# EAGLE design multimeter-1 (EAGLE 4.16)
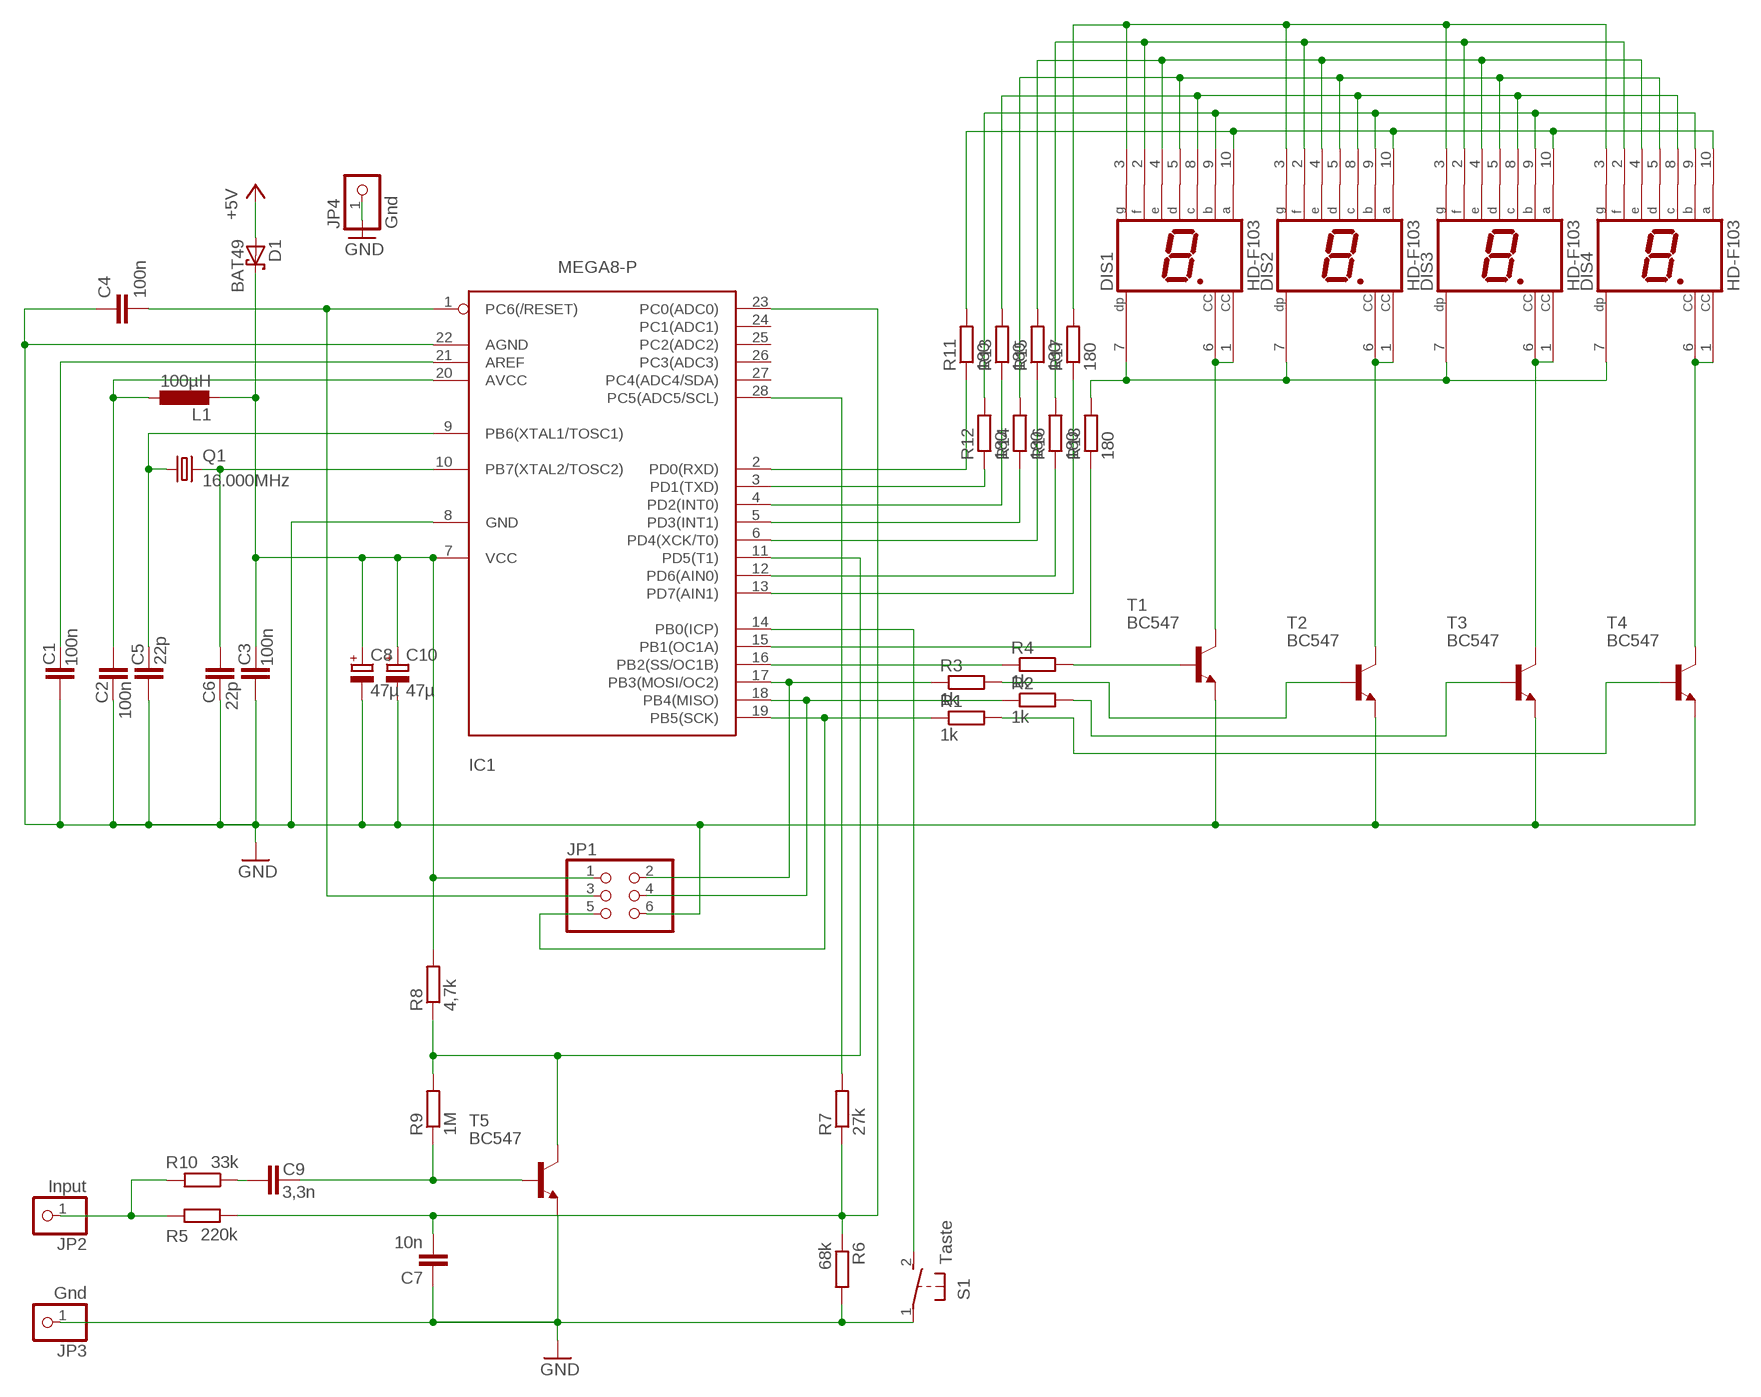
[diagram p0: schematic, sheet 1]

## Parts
C1  100n  C-EU025-030X050  [C025-030X050]
C2  100n  C-EU025-030X050  [C025-030X050]
C3  100n  C-EU025-030X050  [C025-030X050]
C4  100n  C-EU025-030X050  [C025-030X050]
C5  22p  C-EU025-030X050  [C025-030X050]
C6  22p  C-EU025-030X050  [C025-030X050]
C7  10n  C-EU025-030X050  [C025-030X050]
C8  47µ  CPOL-EUE2.5-5  [E2,5-5]
C9  3,3n  C-EU025-030X050  [C025-030X050]
C10  47µ  CPOL-EUE2.5-5  [E2,5-5]
D1  BAT49  [DO41-10]
DIS1  HD-F103  [HDSP-E]
DIS2  HD-F103  [HDSP-E]
DIS3  HD-F103  [HDSP-E]
DIS4  HD-F103  [HDSP-E]
IC1  MEGA8-P  [DIL28-3]
JP1  PINHD-2X3  [2X03]
JP2  Input  PINHD-1X1  [1X01]
JP3  Gnd  PINHD-1X1  [1X01]
JP4  Gnd  PINHD-1X1  [1X01]
L1  100µH  L-EU0207/2V  [0207/2V]
Q1  16.000MHz  CRYSTALHC49S  [HC49/S]
R1  1k  R-EU_0204/7  [0204/7]
R2  1k  R-EU_0204/7  [0204/7]
R3  1k  R-EU_0204/7  [0204/7]
R4  1k  R-EU_0204/7  [0204/7]
R5  220k  R-EU_0204/7  [0204/7]
R6  68k  R-EU_0204/7  [0204/7]
R7  27k  R-EU_0204/7  [0204/7]
R8  4,7k  R-EU_0204/7  [0204/7]
R9  1M  R-EU_0204/7  [0204/7]
R10  33k  R-EU_0204/7  [0204/7]
R11  180  R-EU_0204/7  [0204/7]
R12  180  R-EU_0204/7  [0204/7]
R13  180  R-EU_0204/7  [0204/7]
R14  180  R-EU_0204/7  [0204/7]
R15  180  R-EU_0204/7  [0204/7]
R16  180  R-EU_0204/7  [0204/7]
R17  180  R-EU_0204/7  [0204/7]
R18  180  R-EU_0204/7  [0204/7]
S1  Taste  31-XX  [B3F-31XX]
T1  BC547  [TO92]
T2  BC547  [TO92]
T3  BC547  [TO92]
T4  BC547  [TO92]
T5  BC547  [TO92]

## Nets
+5V: D1.A
GND: C1.1 C2.1 C3.1 C4.1 C5.1 C6.1 C7.1 C8.- C10.- IC1.8(GND) IC1.22(AGND) JP1.6 JP3.1 JP4.1 R6.2 S1.1(P) T1.1(E) T2.1(E) T3.1(E) T4.1(E) T5.1(E)
N$1: C4.2 IC1.1(PC6(/RESET)) JP1.3
N$2: C1.2 IC1.21(AREF)
N$3: C2.2 IC1.20(AVCC) L1.1
N$4: IC1.3(PD1(TXD)) R12.1
N$5: C5.2 IC1.9(PB6(XTAL1/TOSC1)) Q1.1
N$6: C6.2 IC1.10(PB7(XTAL2/TOSC2)) Q1.2
N$7: IC1.4(PD2(INT0)) R13.1
N$8: DIS1.10(A) DIS2.10(A) DIS3.10(A) DIS4.10(A) R11.2
N$9: DIS1.9(B) DIS2.9(B) DIS3.9(B) DIS4.9(B) R12.2
N$10: DIS1.8(C) DIS2.8(C) DIS3.8(C) DIS4.8(C) R13.2
N$11: DIS1.5(D) DIS2.5(D) DIS3.5(D) DIS4.5(D) R14.2
N$12: DIS1.4(E) DIS2.4(E) DIS3.4(E) DIS4.4(E) R15.2
N$13: DIS1.3(G) DIS2.3(G) DIS3.3(G) DIS4.3(G) R17.2
N$14: DIS1.2(F) DIS2.2(F) DIS3.2(F) DIS4.2(F) R16.2
N$15: DIS1.7(DP) DIS2.7(DP) DIS3.7(DP) DIS4.7(DP) R18.2
N$16: DIS1.1(CC) DIS1.6(CC) T1.3(C)
N$17: DIS2.1(CC) DIS2.6(CC) T2.3(C)
N$18: DIS3.1(CC) DIS3.6(CC) T3.3(C)
N$19: DIS4.1(CC) DIS4.6(CC) T4.3(C)
N$20: IC1.19(PB5(SCK)) JP1.5 R1.1
N$21: IC1.5(PD3(INT1)) R14.1
N$22: IC1.2(PD0(RXD)) R11.1
N$23: IC1.6(PD4(XCK/T0)) R15.1
N$24: IC1.12(PD6(AIN0)) R16.1
N$25: IC1.13(PD7(AIN1)) R17.1
N$26: IC1.15(PB1(OC1A)) R18.1
N$27: IC1.18(PB4(MISO)) JP1.4 R2.1
N$28: IC1.17(PB3(MOSI/OC2)) JP1.2 R3.1
N$29: IC1.16(PB2(SS/OC1B)) R4.1
N$30: R4.2 T1.2(B)
N$31: R3.2 T2.2(B)
N$32: R2.2 T3.2(B)
N$33: R1.2 T4.2(B)
N$34: C7.2 IC1.23(PC0(ADC0)) R5.2 R6.1 R7.1
N$35: C9.2 R10.1
N$36: JP2.1 R5.1 R10.2
N$37: IC1.14(PB0(ICP)) S1.2(S)
N$38: IC1.28(PC5(ADC5/SCL)) R7.2
N$40: IC1.11(PD5(T1)) R8.1 R9.2 T5.3(C)
N$42: C9.1 R9.1 T5.2(B)
VCC: C3.2 C8.+ C10.+ D1.C IC1.7(VCC) JP1.1 L1.2 R8.2
Unconnected: IC1.24(PC1(ADC1)) IC1.25(PC2(ADC2)) IC1.26(PC3(ADC3)) IC1.27(PC4(ADC4/SDA))

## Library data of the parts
C1-C7 C9 = rcl:C-EU: CAPACITOR, European symbol
C8 C10 = rcl:CPOL-EU: POLARIZED CAPACITOR, European symbol
D1 = diode:BAT49: DIODE
DIS1-DIS4 = display-hp:HD-F103: LED DISPLAY 1-character 7 segment, decimal point right
IC1 = atmel:MEGA8-P: MICROCONTROLLER 8 Kbytes FLASH 1 kbytes SRAM 512 bytes EEPROM USART 4-channel 10 bit ADC 2-channel 8 bit ADC Source: avr.lbr
JP1 = pinhead:PINHD-2X3: PIN HEADER
JP2-JP4 = pinhead:PINHD-1X1: PIN HEADER
L1 = rcl:L-EU: INDUCTOR, European symbol
Q1 = crystal:CRYSTAL: CRYSTAL
R1-R18 = rcl:R-EU_: RESISTOR, European symbol
S1 = switch-omron:31-XX: OMRON SWITCH
T1-T5 = transistor:BC547: NPN TRANSISTOR

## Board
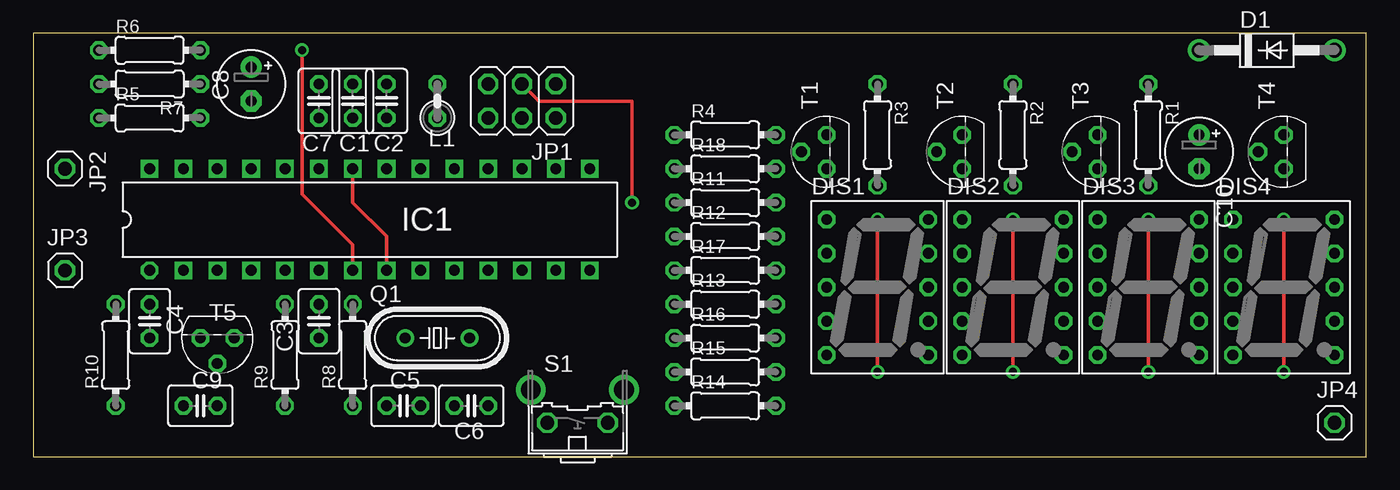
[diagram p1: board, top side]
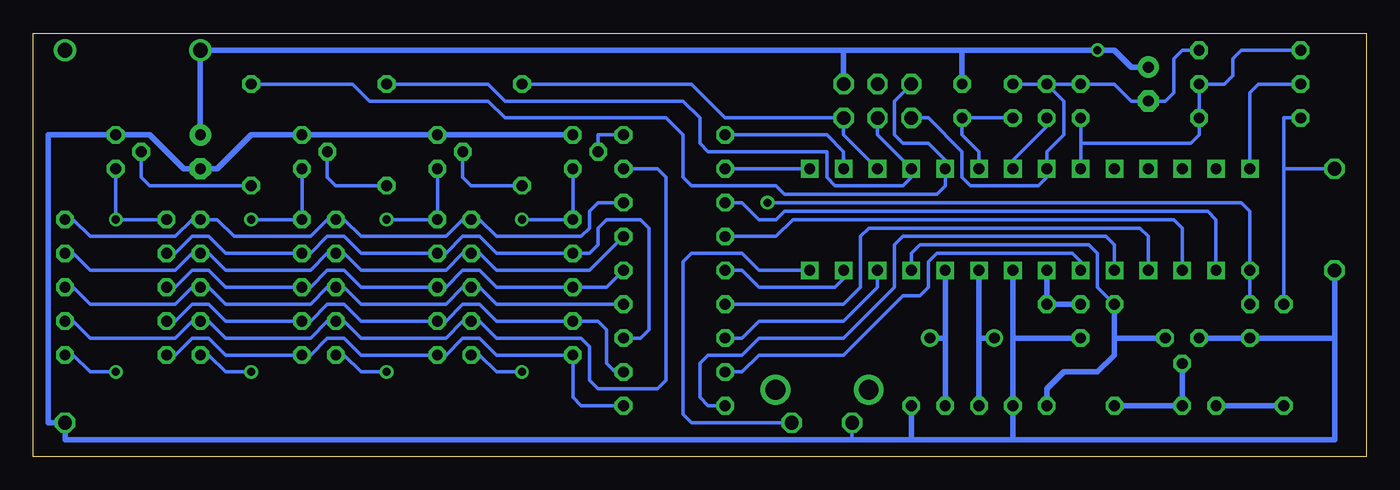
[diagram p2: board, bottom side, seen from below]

Size 100 x 31.74 mm. Coordinates in mm from the lower left corner, seen from the top.
Outline: 0,0 100,0 100,31.74 0,31.74 0,0
Copper layers (1*16): Top 0.035mm / dielectric 1.5mm / Bottom 0.035mm
Design rules "default": minimum track width 10mil, minimum drill 24mil, track to track 8mil, track to pad 8mil, pad to pad 8mil, via to via 8mil, smd to smd 8mil, copper to edge 40mil, drill to drill 8mil, minimum pad ring 10mil, minimum via ring 8mil, stop-mask expansion 4mil, vias tented up to drill 0mil, thermal gap 10mil

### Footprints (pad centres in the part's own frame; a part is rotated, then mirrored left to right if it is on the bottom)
C025-030X050 = drill 0.813 octagon: 1 -1.27,0; 2 1.27,0
E2,5-5 = drill 0.813 pad 1.6 round: + -1.27,0 | drill 0.813 pad 1.6 octagon: - 1.27,0
DO41-10 = drill 1.118 round: A 5.08,0; C -5.08,0
HDSP-E = drill 0.813 octagon: 1 -3.81,5.08; 2 -3.81,2.54; 3 -3.81,0; 4 -3.81,-2.54; 5 -3.81,-5.08; 6 3.81,-5.08; 7 3.81,-2.54; 8 3.81,0; 9 3.81,2.54; 10 3.81,5.08
DIL28-3 = drill 0.813 octagon: 1 -16.51,-3.81 | drill 0.813 square: 2 -13.97,-3.81; 3 -11.43,-3.81; 4 -8.89,-3.81; 5 -6.35,-3.81; 6 -3.81,-3.81; 7 -1.27,-3.81; 8 1.27,-3.81; 9 3.81,-3.81; 10 6.35,-3.81; 11 8.89,-3.81; 12 11.43,-3.81; 13 13.97,-3.81; 14 16.51,-3.81; 15 16.51,3.81; 16 13.97,3.81; 17 11.43,3.81; 18 8.89,3.81; 19 6.35,3.81; 20 3.81,3.81; 21 1.27,3.81; 22 -1.27,3.81; 23 -3.81,3.81; 24 -6.35,3.81; 25 -8.89,3.81; 26 -11.43,3.81; 27 -13.97,3.81; 28 -16.51,3.81
2X03 = drill 1.016 octagon: 1 -2.54,-1.27; 2 -2.54,1.27; 3 0,-1.27; 4 0,1.27; 5 2.54,-1.27; 6 2.54,1.27
1X01 = drill 1.016 octagon: 1 0,0
0207/2V = drill 0.813 octagon: 1 -1.27,0; 2 1.27,0
HC49/S = drill 0.813 round: 1 -2.413,0; 2 2.413,0
0204/7 = drill 0.813 octagon: 1 -3.81,0; 2 3.81,0
B3F-31XX = drill 1.016 octagon: 1 -2.261,-1.245; 2 2.261,-1.245 | drill 1.499 pad 2.159 round: 3 -3.505,1.245; 4 3.505,1.245
TO92 = drill 0.813 octagon: 1 1.27,0; 2 0,1.905; 3 -1.27,0

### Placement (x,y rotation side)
C1  23.96,26.67 270 top
C2  26.51,26.67 270 top
C3  21.43,10.15 90 top
C4  8.73,10.15 90 top
C5  27.78,3.81 0 top
C6  32.86,3.81 180 top
C7  21.43,26.67 270 top
C8  16.35,27.94 270 top
C9  12.54,3.81 180 top
C10  87.46,22.86 270 top
D1  92.54,30.48 0 top
DIS1  63.34,12.69 0 top
DIS2  73.49,12.69 0 top
DIS3  83.65,12.69 0 top
DIS4  93.81,12.69 0 top
IC1  25.23,17.78 0 top
JP1  36.66,26.67 180 top
JP2  2.38,21.59 270 top
JP3  2.38,13.96 0 top
JP4  97.62,2.54 0 top
L1  30.32,26.67 90 top
Q1  30.32,8.88 0 top
R1  83.65,24.12 270 top
R2  73.49,24.12 270 top
R3  63.34,24.12 270 top
R4  51.91,24.12 0 top
R5  8.73,25.39 0 top
R6  8.73,30.48 0 top
R7  8.73,27.94 180 top
R8  23.96,7.62 90 top
R9  18.89,7.62 90 top
R10  6.18,7.62 90 top
R11  51.91,19.05 0 top
R12  51.91,16.51 0 top
R13  51.91,11.42 0 top
R14  51.91,3.81 0 top
R15  51.91,6.34 0 top
R16  51.91,8.88 0 top
R17  51.91,13.96 0 top
R18  51.91,21.59 0 top
S1  40.83,3.78 0 top
T1  59.52,22.86 90 top
T2  69.68,22.86 90 top
T3  79.84,22.86 90 top
T4  93.81,22.86 90 top
T5  13.81,8.88 180 top

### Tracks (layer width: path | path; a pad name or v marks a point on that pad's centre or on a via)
GND
  Top 0.254: IC1.8 26.51,16.51 23.96,19.05 IC1.22
  Bottom 0.254: C1.1 C7.1 18.89,27.94 17.62,26.67 C8.- 15.08,26.67 14.44,27.3 14.44,29.84 13.81,30.48 R6.2 | C1.1 22.7,26.67 22.7,24.12 23.96,22.86 IC1.22 23.96,20.95 24.6,20.32 29.68,20.32 30.32,20.95 30.32,22.86 32.86,25.39 JP1.6 | C1.1 C2.1 | 38.57,1.27 S1.1
  Bottom 0.406: 2.38,8.88 2.38,1.27 26.51,1.27 | 2.38,8.88 JP3.1 | 26.51,1.27 34.12,1.27 | 34.12,1.27 38.57,1.27 97.62,1.27 JP4.1 98.89,2.54 98.89,24.12 T4.1 91.27,24.12 88.73,21.59 C10.- 86.19,21.59 83.65,24.12 T3.1 T2.1 T1.1 | 26.51,8.88 C5.1 26.51,1.27 | 26.51,8.88 IC1.8 | 34.12,1.27 C6.1 | 26.51,8.88 C3.1 | T5.1 C4.1 2.38,8.88
N$1  (via drill 0.61)
  Top 0.254: v44.92,19.05 44.92,26.67 37.94,26.67 JP1.3
  Bottom 0.254: v44.92,19.05 9.36,19.05 8.73,18.41 IC1.1 C4.2
N$2
  Bottom 0.254: C1.2 23.96,24.76 26.51,22.22 IC1.21
N$3
  Bottom 0.254: C2.2 L1.1 30.32,24.12 29.05,22.86 IC1.20
N$4
  Bottom 0.254: IC1.3 13.81,17.14 14.44,17.78 43.02,17.78 44.29,16.51 R12.1
N$5
  Bottom 0.406: C5.2 29.05,8.88 | 29.05,8.88 IC1.9 | 29.05,8.88 Q1.1
N$6
  Bottom 0.406: C6.2 31.59,8.88 | 31.59,8.88 IC1.10 | 31.59,8.88 Q1.2
N$7
  Bottom 0.254: IC1.4 16.35,16.51 16.98,17.14 37.3,17.14 37.94,16.51 37.94,12.69 39.2,11.42 R13.1
N$8
  Bottom 0.254: DIS4.10 96.99,17.78 95.72,16.51 89.37,16.51 88.1,17.78 DIS3.10 86.19,17.78 84.92,16.51 79.21,16.51 77.94,17.78 DIS2.10 76.67,17.78 75.4,16.51 69.05,16.51 67.78,17.78 DIS1.10 66.51,17.78 65.24,16.51 58.89,16.51 58.26,17.14 58.26,18.41 57.62,19.05 R11.2
N$9
  Bottom 0.254: DIS4.9 96.99,15.23 95.72,13.96 89.37,13.96 88.1,15.23 DIS3.9 86.83,15.23 85.56,13.96 79.21,13.96 77.94,15.23 DIS2.9 76.67,15.23 75.4,13.96 69.05,13.96 67.78,15.23 DIS1.9 66.51,15.23 65.24,13.96 58.26,13.96 R12.2
N$10
  Bottom 0.254: DIS4.8 96.99,12.69 95.72,11.42 89.37,11.42 88.1,12.69 DIS3.8 86.83,12.69 85.56,11.42 79.21,11.42 77.94,12.69 DIS2.8 76.67,12.69 75.4,11.42 69.05,11.42 67.78,12.69 DIS1.8 66.51,12.69 65.24,11.42 R13.2
N$11
  Bottom 0.254: DIS4.5 89.37,7.62 88.1,8.88 86.83,8.88 85.56,7.62 DIS3.5 79.21,7.62 77.94,8.88 76.67,8.88 75.4,7.62 DIS2.5 69.05,7.62 67.78,8.88 66.51,8.88 65.24,7.62 DIS1.5 59.52,4.44 58.89,3.81 R14.2
N$12
  Bottom 0.254: DIS4.4 89.37,10.15 88.1,11.42 86.83,11.42 85.56,10.15 DIS3.4 79.21,10.15 77.94,11.42 76.67,11.42 75.4,10.15 DIS2.4 69.05,10.15 67.78,11.42 66.51,11.42 65.24,10.15 DIS1.4 57.62,10.15 56.98,9.52 56.98,6.98 56.35,6.34 R15.2
N$13
  Bottom 0.254: DIS4.3 89.37,12.69 88.1,13.96 86.83,13.96 85.56,12.69 DIS3.3 79.21,12.69 77.94,13.96 76.67,13.96 75.4,12.69 DIS2.3 69.05,12.69 67.78,13.96 66.51,13.96 65.24,12.69 DIS1.3 56.98,12.69 R17.2
N$14
  Bottom 0.254: DIS4.2 89.37,15.23 88.1,16.51 86.83,16.51 85.56,15.23 DIS3.2 79.21,15.23 77.94,16.51 76.67,16.51 75.4,15.23 DIS2.2 69.05,15.23 67.78,16.51 66.51,16.51 65.24,15.23 DIS1.2 58.26,15.23 57.62,15.87 57.62,17.14 56.98,17.78 54.45,17.78 53.81,17.14 53.81,9.52 54.45,8.88 R16.2
N$15
  Bottom 0.254: DIS4.7 96.99,10.15 95.72,8.88 89.37,8.88 88.1,10.15 DIS3.7 86.83,10.15 85.56,8.88 79.21,8.88 77.94,10.15 DIS2.7 76.67,10.15 75.4,8.88 69.05,8.88 67.78,10.15 DIS1.7 66.51,10.15 65.24,8.88 58.89,8.88 58.26,8.25 58.26,5.71 57.62,5.08 53.18,5.08 52.54,5.71 52.54,20.95 53.18,21.59 R18.2
N$16  (via drill 0.61 pad 1.02)
  Top 0.254: v63.34,6.34 v63.34,17.78
  Bottom 0.254: v63.34,6.34 65.24,6.34 66.51,7.62 DIS1.6 | v63.34,17.78 DIS1.1 T1.3
N$17  (via drill 0.61 pad 1.02)
  Top 0.254: v73.49,6.34 v73.49,17.78
  Bottom 0.254: v73.49,6.34 75.4,6.34 76.67,7.62 DIS2.6 | v73.49,17.78 DIS2.1 T2.3
N$18  (via drill 0.61 pad 1.02)
  Top 0.254: v83.65,6.34 v83.65,17.78
  Bottom 0.254: v83.65,6.34 85.56,6.34 86.83,7.62 DIS3.6 | v83.65,17.78 DIS3.1 T3.3
N$19  (via drill 0.61 pad 1.02)
  Top 0.254: v93.81,6.34 v93.81,17.78
  Bottom 0.254: v93.81,6.34 95.72,6.34 96.99,7.62 DIS4.6 | DIS4.1 v93.81,17.78 T4.3
N$20
  Bottom 0.254: JP1.5 35.4,26.67 35.4,24.12 34.76,23.49 32.86,23.49 31.59,22.22 IC1.19 31.59,20.32 32.22,19.68 43.65,19.68 44.29,20.32 50.63,20.32 51.27,20.95 51.27,24.12 52.54,25.39 64.6,25.39 65.88,26.67 74.77,26.67 76.03,27.94 R1.1
N$21
  Bottom 0.254: IC1.5 18.89,15.87 19.52,16.51 34.76,16.51 35.4,15.87 35.4,12.69 39.2,8.88 45.55,8.88 46.83,7.62 49.37,7.62 50,6.98 50,4.44 49.37,3.81 R14.1
N$22
  Bottom 0.254: IC1.2 11.27,17.78 11.9,18.41 43.65,18.41 44.29,17.78 45.55,17.78 46.83,19.05 R11.1
N$23
  Bottom 0.254: IC1.6 21.43,14.6 22.06,15.23 32.22,15.23 32.86,14.6 32.86,12.69 33.49,12.06 34.76,12.06 39.2,7.62 45.55,7.62 46.83,6.34 R15.1
N$24
  Bottom 0.254: IC1.12 36.66,12.69 39.2,10.15 45.55,10.15 46.83,8.88 R16.1
N$25
  Bottom 0.254: IC1.13 39.2,13.33 39.84,12.69 45.55,12.69 46.83,13.96 R17.1
N$26
  Bottom 0.254: IC1.15 R18.1
N$27
  Bottom 0.254: R2.1 65.88,27.94 64.6,26.67 51.27,26.67 50,25.39 50,23.49 49.37,22.86 40.48,22.86 40.48,20.95 39.84,20.32 34.76,20.32 34.12,20.95 IC1.18 36.66,24.12 JP1.4
N$28
  Bottom 0.254: R3.1 50.63,27.94 48.09,25.39 JP1.2 39.2,24.12 IC1.17
N$29
  Bottom 0.254: IC1.16 39.2,22.86 40.48,24.12 R4.1
N$30
  Bottom 0.254: T1.2 57.62,24.12 R4.2
N$31
  Bottom 0.254: T2.2 67.78,20.95 67.14,20.32 R3.2
N$32
  Bottom 0.254: T3.2 77.94,20.95 77.3,20.32 R2.2
N$33
  Bottom 0.254: T4.2 91.91,20.95 91.27,20.32 R1.2
N$34
  Bottom 0.254: 21.43,23.49 C7.2 | 21.43,23.49 IC1.23 | 21.43,23.49 13.17,23.49 12.54,24.12 R5.2 R7.1 10.63,27.94 10,28.57 10,29.84 9.36,30.48 R6.1
N$35
  Bottom 0.406: R10.1 C9.2
N$36
  Bottom 0.254: R10.2 6.18,21.59 | 6.18,21.59 JP2.1 | R5.1 6.18,25.39 6.18,21.59
N$37
  Bottom 0.254: IC1.14 45.55,13.96 46.83,15.23 50.63,15.23 51.27,14.6 51.27,3.17 50.63,2.54 S1.2
N$38
  Bottom 0.254: R7.2 8.09,27.94 8.73,27.3 IC1.28
N$40
  Bottom 0.254: IC1.11 34.12,15.23 33.49,15.87 20.79,15.87 20.16,15.23 20.16,12.69 R9.2
  Bottom 0.406: 18.89,8.88 T5.3 | 18.89,8.88 R9.2 | 18.89,8.88 18.89,7.62 20.16,6.34 22.7,6.34 23.96,5.08 R8.1
N$42
  Bottom 0.406: T5.2 C9.1 R9.1
VCC  (via drill 0.61 pad 1.02)
  Top 0.254: v20.16,30.48 20.16,19.68 23.96,15.87 IC1.7
  Bottom 0.406: 30.32,30.48 39.2,30.48 | 39.2,30.48 JP1.1 | 30.32,30.48 v20.16,30.48 18.89,30.48 17.62,29.21 C8.+ | 30.32,30.48 L1.2 | 39.2,30.48 D1.C C10.+ | C3.2 R8.2 IC1.7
